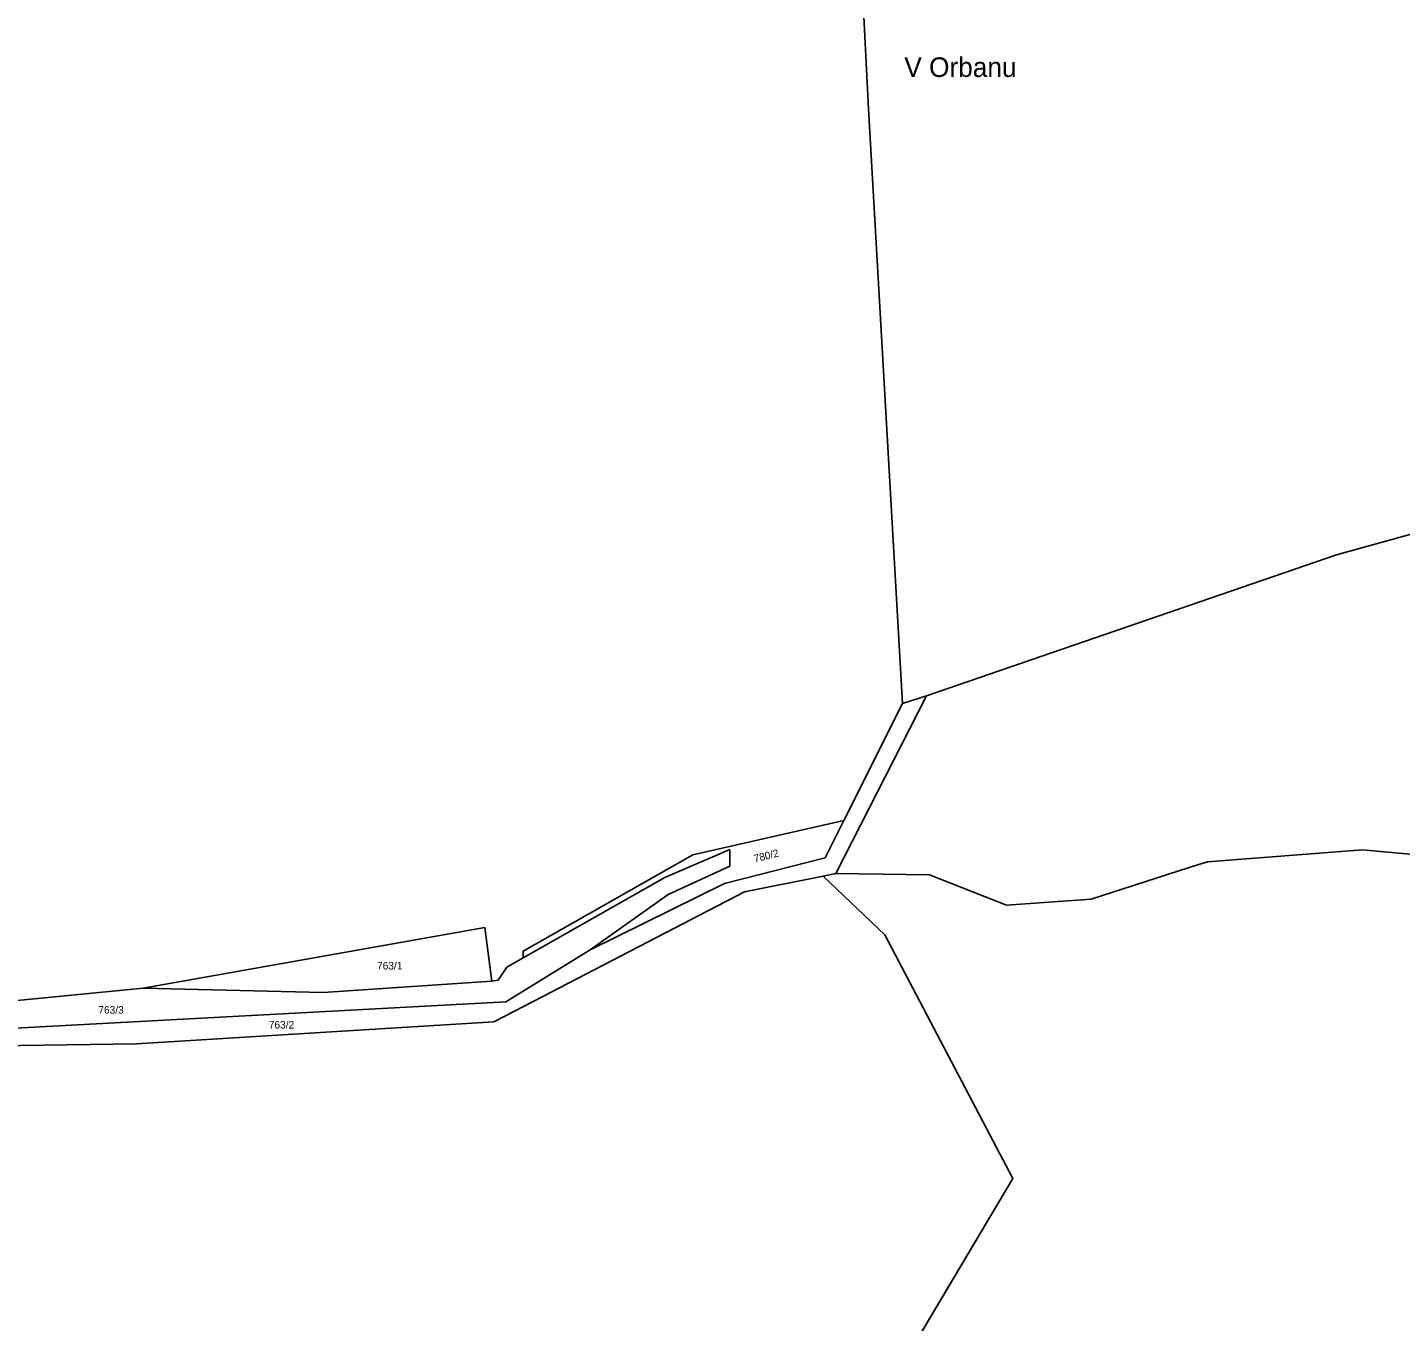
# Model space of a CAD drawing. Extents: x -580551 to -575069, y -1073031 to -1067931.
# Drawn here: x -578363.2 to -578055, y -1071557 to -1071266.5 of the extents above; entities that cross this region are included whole.
import ezdxf

# ---------------------------------------------------------------- set-up
doc = ezdxf.new("R2010")
doc.units = 0
for name, color, linetype in [('Hranice z DKM', 7, 'Continuous'), ('Názvosloví', 7, 'Continuous'), ('Parcela', 7, 'Continuous'), ('Parcelní číslo', 7, 'Continuous')]:
    doc.layers.add(name, color=color, linetype=linetype)

msp = doc.modelspace()

# ---------------------------------------------------------------- linework, layer by layer
at = {"layer": 'Hranice z DKM'}
for points in [[(-578181.75, -1071456.47), (-578184.62, -1071457.04), (-578170.75, -1071470.23)], [(-578170.75, -1071470.23), (-578147.28, -1071514.94), (-578142.04, -1071524.92), (-578176.29, -1071582.56), (-578207.78, -1071667.74), (-578214.44, -1071682.67), (-578250.82, -1071674.55), (-578266.19, -1071705.92), (-578278.37, -1071702.13)]]:
    msp.add_lwpolyline(points, dxfattribs=at)
at = {"layer": 'Parcela'}
for p, q in [((-578181.24, -1071150.54), (-578174.47, -1071284.82)), ((-578174.47, -1071284.82), (-578166.82, -1071418.32)), ((-578012.72, -1071369.11), (-578069.43, -1071384.92)), ((-578069.43, -1071384.92), (-578161.41, -1071416.58)), ((-578181.75, -1071456.47), (-578161.41, -1071416.58)), ((-578161.41, -1071416.58), (-578166.82, -1071418.32)), ((-578166.82, -1071418.32), (-578180.01, -1071444.52)), ((-578180.01, -1071444.52), (-578213.86, -1071452.24)), ((-578180.01, -1071444.52), (-578184.15, -1071452.96)), ((-578205.55, -1071451.06), (-578220.13, -1071457.35)), ((-578205.57, -1071454.79), (-578205.55, -1071451.06)), ((-578063.54, -1071451.15), (-578098.37, -1071453.82)), ((-578035.47, -1071453.71), (-578063.54, -1071451.15)), ((-578213.86, -1071452.24), (-578251.93, -1071473.87)), ((-578184.15, -1071452.96), (-578206.74, -1071458.71)), ((-578098.37, -1071453.82), (-578102.43, -1071455.13)), ((-578220.13, -1071457.35), (-578251.93, -1071475.37)), ((-578219.39, -1071461.17), (-578205.57, -1071454.79)), ((-578184.62, -1071457.04), (-578202.3, -1071460.56)), ((-578181.75, -1071456.47), (-578184.62, -1071457.04)), ((-578170.75, -1071470.23), (-578184.62, -1071457.04)), ((-578160.72, -1071456.74), (-578181.75, -1071456.47)), ((-578143.44, -1071463.58), (-578160.72, -1071456.74)), ((-578102.43, -1071455.13), (-578124.46, -1071462.24)), ((-578202.3, -1071460.56), (-578251.77, -1071486.24)), ((-578206.74, -1071458.71), (-578236.96, -1071473.59)), ((-578236.96, -1071473.59), (-578219.39, -1071461.17)), ((-578124.46, -1071462.24), (-578143.44, -1071463.58)), ((-578337.23, -1071482.16), (-578260.59, -1071468.54)), ((-578260.59, -1071468.54), (-578258.97, -1071480.6)), ((-578147.28, -1071514.94), (-578170.75, -1071470.23)), ((-578236.96, -1071473.59), (-578255.84, -1071485.26)), ((-578251.93, -1071475.37), (-578255.6, -1071477.45)), ((-578251.93, -1071473.87), (-578251.93, -1071475.37)), ((-578255.6, -1071477.45), (-578257.58, -1071480.43)), ((-578370.22, -1071485.41), (-578337.23, -1071482.16)), ((-578296.84, -1071483.14), (-578337.23, -1071482.16)), ((-578258.97, -1071480.6), (-578296.84, -1071483.14)), ((-578257.58, -1071480.43), (-578258.97, -1071480.6)), ((-578255.84, -1071485.26), (-578390.8, -1071492.55)), ((-578251.77, -1071486.24), (-578258.55, -1071489.76)), ((-578258.55, -1071489.76), (-578338.79, -1071494.68)), ((-578338.79, -1071494.68), (-578373, -1071495.22)), ((-578142.04, -1071524.92), (-578147.28, -1071514.94)), ((-578176.29, -1071582.56), (-578142.04, -1071524.92))]:
    msp.add_line(p, q, dxfattribs=at)

# ---------------------------------------------------------------- texts
at = {"layer": 'Názvosloví'}
msp.add_text('V Orbanu', height=4.4, dxfattribs=at).set_placement((-578166.404, -1071277.65))
at = {"layer": 'Parcelní číslo'}
msp.add_text('780/2', height=1.7, rotation=13.80828, dxfattribs=at).set_placement((-578199.966, -1071453.981))
for s, p in [('763/1', (-578284.764, -1071478)), ('763/3', (-578347.317, -1071487.92)), ('763/2', (-578309.056, -1071491.26))]:
    msp.add_text(s, height=1.7, dxfattribs=at).set_placement(p)

doc.saveas('drawing.dxf')
